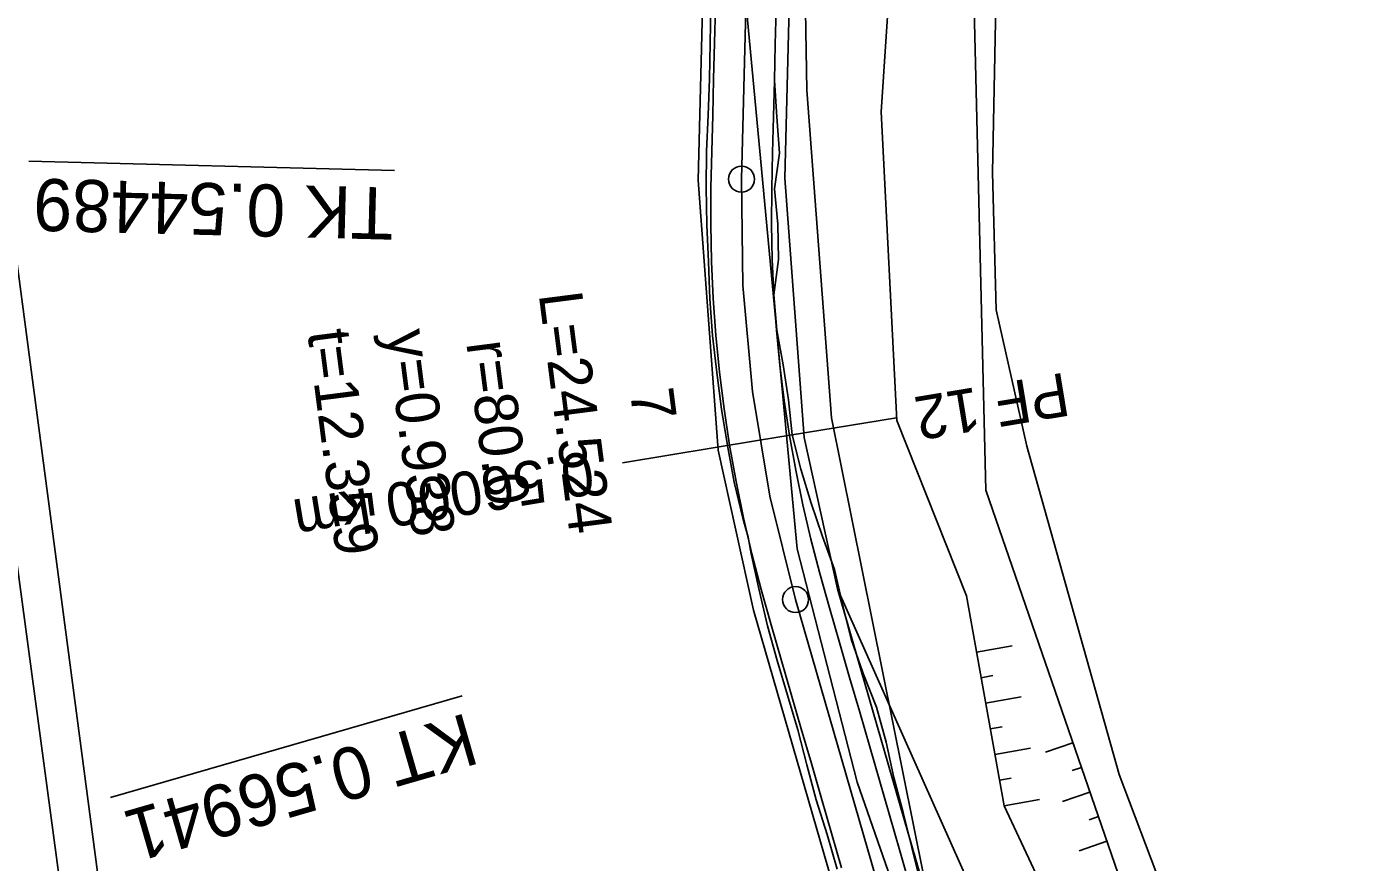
# Model space of a CAD drawing. Extents: x -555887 to -552101, y -1100251 to -1096546.
# Drawn here: x -553957.5 to -553879.9, y -1098150.5 to -1098102.3 of the extents above; entities that cross this region are included whole.
import ezdxf

# ---------------------------------------------------------------- set-up
doc = ezdxf.new("R2010")
doc.units = 0
for name, color, linetype in [('07_KANALIZACE', 7, 'Continuous'), ('07_VODOVOD', 7, 'Continuous'), ('PARCELY_cesty', 7, 'Continuous'), ('PARCELY_VHO', 7, 'Continuous'), ('POLYGONY_SITUACE_PF', 7, 'Continuous'), ('POLYGONY_SITUACE_PF_POPISY', 7, 'Continuous'), ('POLYGONY_SITUACE_PO', 7, 'Continuous'), ('ZSST', 7, 'Continuous'), ('zájem', 7, 'Continuous')]:
    doc.layers.add(name, color=color, linetype=linetype)

msp = doc.modelspace()

# ---------------------------------------------------------------- linework, layer by layer
for p, q in [((-553936.324, -1098110.589), (-553957.409, -1098110.056)), ((-553932.427, -1098140.875), (-553952.691, -1098146.729))]:
    msp.add_line(p, q)
at = {"layer": '07_KANALIZACE'}
msp.add_lwpolyline([(-553933.89, -1098299.13), (-553960.89, -1098094.71), (-553961.69, -1098093.49), (-553975.36, -1098088.42), (-553976.47, -1098087.2), (-553997.02, -1097931.32), (-553999.16, -1097907.75), (-553999.72, -1097884.17), (-554000.634, -1097884.273), (-554001.151, -1097883.391), (-554017.16, -1097885.22), (-554171.94, -1097905.19), (-554183.71, -1097906.5), (-554193.28, -1097906.43), (-554202.55, -1097905.69), (-554209.215, -1097906.283), (-554215.09, -1097906.8), (-554226.01, -1097910.87), (-554237.13, -1097913.33)], dxfattribs=at)
at = {"layer": '07_VODOVOD'}
msp.add_lwpolyline([(-553936.175, -1098296.386), (-554003.21, -1097797.26), (-554016.58, -1097798.55), (-554021.42, -1097763.29), (-554007.81, -1097761.46), (-554017.883, -1097690.586), (-554019.47, -1097678.04), (-553931.71, -1097666.8), (-553860.51, -1097660.95), (-553851.186, -1097659.979), (-553809.175, -1097658.756), (-553772.306, -1097657.572), (-553745.69, -1097656.809), (-553714.889, -1097655.5), (-553705.569, -1097655.382), (-553663.409, -1097654.214), (-553621.83, -1097652.811), (-553564.872, -1097648.296)], dxfattribs=at)
at = {"layer": 'PARCELY_cesty'}
for points in [[(-553894.521, -1098237.552), (-553902.872, -1098185.471), (-553908.173, -1098161.777), (-553915.637, -1098135.941), (-553917.674, -1098126.716), (-553918.832, -1098111.157), (-553915.214, -1097968.237), (-553915.615, -1097956.495), (-553918.446, -1097924.391)], [(-553889.599, -1098236.663), (-553897.959, -1098184.529), (-553903.327, -1098160.536), (-553910.789, -1098134.707), (-553912.715, -1098125.988), (-553913.828, -1098111.034), (-553910.368, -1097974.94), (-553910.211, -1097968.215), (-553910.622, -1097956.19), (-553913.42, -1097924.46)]]:
    msp.add_lwpolyline(points, dxfattribs=at)
at = {"layer": 'PARCELY_VHO'}
for points in [[(-553927.41, -1097628.08), (-553920.29, -1097651.1), (-553924.15, -1097670.8), (-553927.014, -1097685.697), (-553927.942, -1097698.335), (-553926.88, -1097721.034), (-553926.037, -1097728.701), (-553924.494, -1097736.179), (-553911.111, -1097775.519), (-553905.076, -1097799.369), (-553903.199, -1097814.131), (-553902.803, -1097824.091), (-553903.498, -1097838.889), (-553913.42, -1097924.2), (-553904.91, -1097952.6), (-553904.09, -1097966.52), (-553910.368, -1097974.94), (-553913.828, -1098111.034), (-553912.715, -1098125.988), (-553910.789, -1098134.707), (-553870.98, -1098223.96)], [(-553873.38, -1098200.91), (-553884.8, -1098171.23), (-553894.57, -1098145.41), (-553899.89, -1098126.48), (-553901.66, -1098118.62), (-553901.87, -1098110.72), (-553901.16, -1098074.95), (-553900.96, -1097982.79), (-553898.75, -1097974.9), (-553895.85, -1097967.85), (-553895.42, -1097963.37), (-553895.17, -1097959.49), (-553895.01, -1097951.32), (-553903.94, -1097924.64)]]:
    msp.add_lwpolyline(points, dxfattribs=at)
at = {"layer": 'POLYGONY_SITUACE_PF'}
for p, q in [((-553907.395, -1098124.846), (-553915.288, -1098126.148)), ((-553915.288, -1098126.148), (-553923.181, -1098127.451))]:
    msp.add_line(p, q, dxfattribs=at)
at = {"layer": 'POLYGONY_SITUACE_PO'}
for p, q in [((-553912.713, -1097968.226), (-553916.33, -1098111.096)), ((-553918.095, -1098101.159), (-553918.143, -1098103.242)), ((-553917.829, -1098101.166), (-553917.882, -1098103.248)), ((-553917.829, -1098101.166), (-553917.882, -1098103.248)), ((-553914.33, -1098101.254), (-553914.383, -1098103.337)), ((-553914.33, -1098101.254), (-553914.383, -1098103.337)), ((-553914.33, -1098101.254), (-553914.383, -1098103.337)), ((-553918.143, -1098103.242), (-553918.165, -1098105.325)), ((-553917.882, -1098103.248), (-553917.935, -1098105.331)), ((-553917.882, -1098103.248), (-553917.935, -1098105.331)), ((-553914.383, -1098103.337), (-553914.436, -1098105.42)), ((-553914.383, -1098103.337), (-553914.436, -1098105.42)), ((-553914.383, -1098103.337), (-553914.436, -1098105.42)), ((-553918.165, -1098105.325), (-553918.254, -1098107.407)), ((-553917.935, -1098105.331), (-553917.987, -1098107.414)), ((-553917.935, -1098105.331), (-553917.987, -1098107.414)), ((-553914.436, -1098105.42), (-553914.488, -1098107.502)), ((-553914.436, -1098105.42), (-553914.488, -1098107.502)), ((-553914.436, -1098105.42), (-553914.436, -1098105.42)), ((-553914.436, -1098105.42), (-553914.293, -1098107.507)), ((-553918.254, -1098107.407), (-553918.355, -1098109.488)), ((-553917.987, -1098107.414), (-553918.04, -1098109.496)), ((-553917.987, -1098107.414), (-553918.04, -1098109.496)), ((-553914.488, -1098107.502), (-553914.541, -1098109.585)), ((-553914.488, -1098107.502), (-553914.541, -1098109.585)), ((-553914.293, -1098107.507), (-553914.134, -1098109.595)), ((-553918.355, -1098109.488), (-553918.359, -1098111.586)), ((-553918.04, -1098109.496), (-553918.088, -1098111.591)), ((-553918.04, -1098109.496), (-553918.088, -1098111.591)), ((-553914.541, -1098109.585), (-553914.589, -1098111.656)), ((-553914.541, -1098109.585), (-553914.589, -1098111.656)), ((-553914.134, -1098109.595), (-553914.418, -1098111.659)), ((-553918.359, -1098111.586), (-553918.326, -1098113.721)), ((-553918.088, -1098111.591), (-553918.101, -1098113.719)), ((-553918.088, -1098111.591), (-553918.101, -1098113.719)), ((-553916.33, -1098111.096), (-553916.25, -1098117.225)), ((-553914.589, -1098111.656), (-553914.601, -1098113.694)), ((-553914.589, -1098111.656), (-553914.601, -1098113.694)), ((-553914.418, -1098111.659), (-553914.23, -1098113.691)), ((-553918.326, -1098113.721), (-553918.226, -1098115.853)), ((-553918.101, -1098113.719), (-553918.057, -1098115.848)), ((-553918.101, -1098113.719), (-553918.057, -1098115.848)), ((-553914.601, -1098113.694), (-553914.559, -1098115.731)), ((-553914.601, -1098113.694), (-553914.559, -1098115.731)), ((-553914.23, -1098113.691), (-553914.198, -1098115.719)), ((-553918.226, -1098115.853), (-553918.147, -1098117.985)), ((-553918.057, -1098115.848), (-553917.956, -1098117.974)), ((-553918.057, -1098115.848), (-553917.956, -1098117.974)), ((-553914.559, -1098115.731), (-553914.462, -1098117.766)), ((-553914.559, -1098115.731), (-553914.462, -1098117.766)), ((-553914.198, -1098115.719), (-553914.462, -1098117.766)), ((-553917.956, -1098117.974), (-553917.802, -1098120.097)), ((-553917.956, -1098117.974), (-553917.802, -1098120.097)), ((-553916.25, -1098117.225), (-553915.702, -1098123.329)), ((-553914.462, -1098117.766), (-553914.462, -1098117.766)), ((-553914.462, -1098117.766), (-553914.462, -1098117.766)), ((-553914.462, -1098117.766), (-553914.283, -1098119.796)), ((-553914.462, -1098117.766), (-553914.315, -1098119.798)), ((-553914.462, -1098117.766), (-553914.315, -1098119.798)), ((-553918.147, -1098117.985), (-553917.998, -1098120.114)), ((-553917.998, -1098120.114), (-553917.755, -1098122.234)), ((-553917.802, -1098120.097), (-553917.594, -1098122.216)), ((-553917.802, -1098120.097), (-553917.594, -1098122.216)), ((-553914.315, -1098119.798), (-553914.115, -1098121.826)), ((-553914.315, -1098119.798), (-553914.115, -1098121.826)), ((-553914.283, -1098119.796), (-553913.919, -1098121.804)), ((-553914.115, -1098121.826), (-553913.865, -1098123.848)), ((-553914.115, -1098121.826), (-553913.865, -1098123.848)), ((-553913.919, -1098121.804), (-553913.615, -1098123.814)), ((-553917.755, -1098122.234), (-553917.479, -1098124.349)), ((-553917.594, -1098122.216), (-553917.332, -1098124.328)), ((-553917.594, -1098122.216), (-553917.332, -1098124.328)), ((-553915.702, -1098123.329), (-553914.687, -1098129.374)), ((-553913.865, -1098123.848), (-553913.561, -1098125.863)), ((-553913.865, -1098123.848), (-553913.561, -1098125.863)), ((-553913.615, -1098123.814), (-553913.418, -1098125.84)), ((-553917.479, -1098124.349), (-553917.144, -1098126.455)), ((-553917.332, -1098124.328), (-553917.014, -1098126.433)), ((-553917.332, -1098124.328), (-553917.014, -1098126.433)), ((-553917.144, -1098126.455), (-553916.748, -1098128.55)), ((-553917.014, -1098126.433), (-553916.64, -1098128.529)), ((-553917.014, -1098126.433), (-553916.64, -1098128.529)), ((-553913.561, -1098125.863), (-553913.203, -1098127.869)), ((-553913.561, -1098125.863), (-553913.203, -1098127.869)), ((-553913.418, -1098125.84), (-553912.9, -1098127.811)), ((-553913.203, -1098127.869), (-553912.791, -1098129.865)), ((-553913.203, -1098127.869), (-553912.791, -1098129.865)), ((-553912.9, -1098127.811), (-553912.31, -1098129.76)), ((-553916.748, -1098128.55), (-553916.256, -1098130.624)), ((-553916.64, -1098128.529), (-553916.21, -1098130.614)), ((-553916.64, -1098128.529), (-553916.21, -1098130.614)), ((-553914.687, -1098129.374), (-553913.213, -1098135.324)), ((-553912.791, -1098129.865), (-553912.327, -1098131.849)), ((-553912.791, -1098129.865), (-553912.327, -1098131.849)), ((-553912.31, -1098129.76), (-553911.664, -1098131.686)), ((-553916.256, -1098130.624), (-553915.951, -1098131.719)), ((-553916.21, -1098130.614), (-553915.725, -1098132.687)), ((-553916.21, -1098130.614), (-553915.725, -1098132.687)), ((-553915.951, -1098131.719), (-553915.766, -1098132.697)), ((-553912.327, -1098131.849), (-553911.811, -1098133.82)), ((-553912.327, -1098131.849), (-553911.811, -1098133.82)), ((-553911.664, -1098131.686), (-553910.975, -1098133.591)), ((-553915.766, -1098132.697), (-553915.309, -1098134.78)), ((-553915.725, -1098132.687), (-553915.186, -1098134.746)), ((-553915.725, -1098132.687), (-553915.186, -1098134.746)), ((-553911.811, -1098133.82), (-553911.253, -1098135.803)), ((-553911.811, -1098133.82), (-553911.253, -1098135.803)), ((-553910.975, -1098133.591), (-553910.509, -1098135.588)), ((-553915.309, -1098134.78), (-553914.822, -1098136.834)), ((-553915.186, -1098134.746), (-553914.615, -1098136.774)), ((-553915.186, -1098134.746), (-553914.615, -1098136.774)), ((-553913.213, -1098135.324), (-553905.75, -1098161.157)), ((-553911.253, -1098135.803), (-553910.675, -1098137.804)), ((-553911.253, -1098135.803), (-553910.675, -1098137.804)), ((-553910.509, -1098135.588), (-553910.018, -1098137.615)), ((-553914.822, -1098136.834), (-553914.273, -1098138.844)), ((-553914.615, -1098136.774), (-553914.037, -1098138.776)), ((-553914.615, -1098136.774), (-553914.037, -1098138.776)), ((-553910.675, -1098137.804), (-553910.096, -1098139.806)), ((-553910.675, -1098137.804), (-553910.096, -1098139.806)), ((-553910.018, -1098137.615), (-553909.314, -1098139.58)), ((-553914.273, -1098138.844), (-553913.682, -1098140.841)), ((-553914.037, -1098138.776), (-553913.459, -1098140.777)), ((-553914.037, -1098138.776), (-553913.459, -1098140.777)), ((-553909.314, -1098139.58), (-553908.549, -1098141.527)), ((-553910.096, -1098139.806), (-553909.518, -1098141.807)), ((-553910.096, -1098139.806), (-553909.518, -1098141.807)), ((-553913.682, -1098140.841), (-553913.09, -1098142.839)), ((-553913.459, -1098140.777), (-553912.881, -1098142.779)), ((-553913.459, -1098140.777), (-553912.881, -1098142.779)), ((-553909.518, -1098141.807), (-553908.94, -1098143.809)), ((-553909.518, -1098141.807), (-553908.94, -1098143.809)), ((-553908.549, -1098141.527), (-553907.989, -1098143.534)), ((-553912.881, -1098142.779), (-553912.302, -1098144.78)), ((-553912.881, -1098142.779), (-553912.302, -1098144.78)), ((-553913.09, -1098142.839), (-553912.561, -1098144.855)), ((-553907.989, -1098143.534), (-553907.543, -1098145.574)), ((-553908.94, -1098143.809), (-553908.362, -1098145.81)), ((-553908.94, -1098143.809), (-553908.362, -1098145.81)), ((-553912.561, -1098144.855), (-553912.033, -1098146.871)), ((-553912.302, -1098144.78), (-553911.724, -1098146.782)), ((-553912.302, -1098144.78), (-553911.724, -1098146.782)), ((-553908.362, -1098145.81), (-553907.784, -1098147.812)), ((-553908.362, -1098145.81), (-553907.784, -1098147.812)), ((-553907.543, -1098145.574), (-553907.021, -1098147.591)), ((-553912.033, -1098146.871), (-553911.393, -1098148.854)), ((-553911.724, -1098146.782), (-553911.146, -1098148.783)), ((-553911.724, -1098146.782), (-553911.146, -1098148.783)), ((-553907.784, -1098147.812), (-553907.205, -1098149.813)), ((-553907.784, -1098147.812), (-553907.205, -1098149.813)), ((-553907.021, -1098147.591), (-553906.519, -1098149.615)), ((-553911.393, -1098148.854), (-553910.806, -1098150.853)), ((-553911.146, -1098148.783), (-553910.568, -1098150.785)), ((-553911.146, -1098148.783), (-553910.568, -1098150.785)), ((-553906.519, -1098149.615), (-553906.012, -1098151.637)), ((-553907.205, -1098149.813), (-553906.627, -1098151.815)), ((-553907.205, -1098149.813), (-553906.627, -1098151.815))]:
    msp.add_line(p, q, dxfattribs=at)
for centre in [(-553916.33, -1098111.096), (-553913.213, -1098135.324)]:
    msp.add_circle(centre, 0.75, dxfattribs=at)
at = {"layer": 'ZSST'}
for p, q in [((-553902.787, -1098138.351), (-553900.736, -1098137.983)), ((-553902.523, -1098139.828), (-553901.84, -1098139.705)), ((-553902.258, -1098141.304), (-553900.207, -1098140.936)), ((-553901.994, -1098142.781), (-553901.31, -1098142.658)), ((-553901.729, -1098144.257), (-553899.677, -1098143.889)), ((-553897.226, -1098143.579), (-553898.815, -1098144.126)), ((-553896.738, -1098144.997), (-553897.267, -1098145.179)), ((-553901.465, -1098145.734), (-553900.781, -1098145.611)), ((-553896.249, -1098146.415), (-553897.838, -1098146.963)), ((-553901.2, -1098147.21), (-553899.148, -1098146.842)), ((-553895.761, -1098147.834), (-553896.29, -1098148.016)), ((-553895.273, -1098149.252), (-553896.861, -1098149.799))]:
    msp.add_line(p, q, dxfattribs=at)
for points in [[(-553903.33, -1097964.72), (-553907.21, -1097972.49), (-553909.82, -1097977.03), (-553910.09, -1097985.04), (-553910.33, -1097998.84), (-553910.24, -1098015.04), (-553911.98, -1098027.76), (-553912.25, -1098046.41), (-553915.41, -1098049.02), (-553915.66, -1098071.91), (-553913.03, -1098078.48), (-553912.56, -1098105.97), (-553911.15, -1098124.85), (-553905.84, -1098151.19), (-553897.79, -1098154.47), (-553892.63, -1098170.29), (-553889.27, -1098181.07), (-553885.09, -1098178.58)], [(-553910.09, -1097985.04), (-553908.92, -1097997.81), (-553908.98, -1098015.37), (-553909.64, -1098027.89), (-553909.58, -1098047.43), (-553907.5, -1098071.18), (-553906.12, -1098074.78), (-553908.27, -1098107.21)], [(-553915.66, -1098071.91), (-553915.58, -1098079.33), (-553916.16, -1098100.06), (-553913.12, -1098132.4), (-553909.66, -1098145.85), (-553902.53, -1098166.3), (-553897.27, -1098194.21), (-553893.66, -1098223.05), (-553891.3, -1098238.44), (-553887.76, -1098249.7), (-553885.71, -1098256.03)], [(-553903.07, -1098094.9), (-553902.24, -1098129.02), (-553893.3, -1098154.98), (-553885.09, -1098178.58)], [(-553908.27, -1098107.21), (-553907.38, -1098125.01), (-553903.37, -1098135.1), (-553901.2, -1098147.21), (-553897.79, -1098154.47)]]:
    msp.add_lwpolyline(points, dxfattribs=at)
at = {"layer": 'zájem'}
for points in [[(-553903.94, -1097924.64), (-553895.01, -1097951.32), (-553895.17, -1097959.49), (-553895.42, -1097963.37), (-553895.85, -1097967.85), (-553898.75, -1097974.9), (-553900.96, -1097982.79), (-553901.16, -1098074.95), (-553901.87, -1098110.72), (-553901.66, -1098118.62), (-553899.89, -1098126.48), (-553894.57, -1098145.41), (-553884.8, -1098171.23), (-553873.38, -1098200.91)], [(-553873.38, -1098200.91), (-553884.8, -1098171.23), (-553894.57, -1098145.41), (-553899.89, -1098126.48), (-553901.66, -1098118.62), (-553901.87, -1098110.72), (-553901.16, -1098074.95), (-553900.96, -1097982.79), (-553898.75, -1097974.9), (-553895.85, -1097967.85), (-553895.42, -1097963.37), (-553895.17, -1097959.49), (-553895.01, -1097951.32), (-553903.94, -1097924.64)]]:
    msp.add_lwpolyline(points, dxfattribs=at)

# ---------------------------------------------------------------- texts
for s, height, rotation, p in [('TK 0.54489', 3, 178.54958, (-553936.349, -1098111.589)), ('L=24.524', 2.5, 277.33153, (-553928.018, -1098117.721)), ('t=12.359', 2.5, 277.33153, (-553941.349, -1098119.901)), ('y=0.938', 2.5, 277.33153, (-553936.809, -1098119.918)), ('r=80.0', 2.5, 277.33153, (-553932.194, -1098120.527)), ('7', 2.5, 277.33153, (-553922.765, -1098123.288)), ('KT 0.56941', 3, 196.11347, (-553932.149, -1098141.835))]:
    msp.add_text(s, height=height, rotation=rotation).set_placement(p)
at = {"layer": 'POLYGONY_SITUACE_PF_POPISY'}
for s, p in [('PF 12', (-553897.691, -1098122.23)), ('0.56000 km', (-553925.073, -1098126.75))]:
    msp.add_text(s, height=2.5, rotation=189.37215, dxfattribs=at).set_placement(p)

doc.saveas('drawing.dxf')
